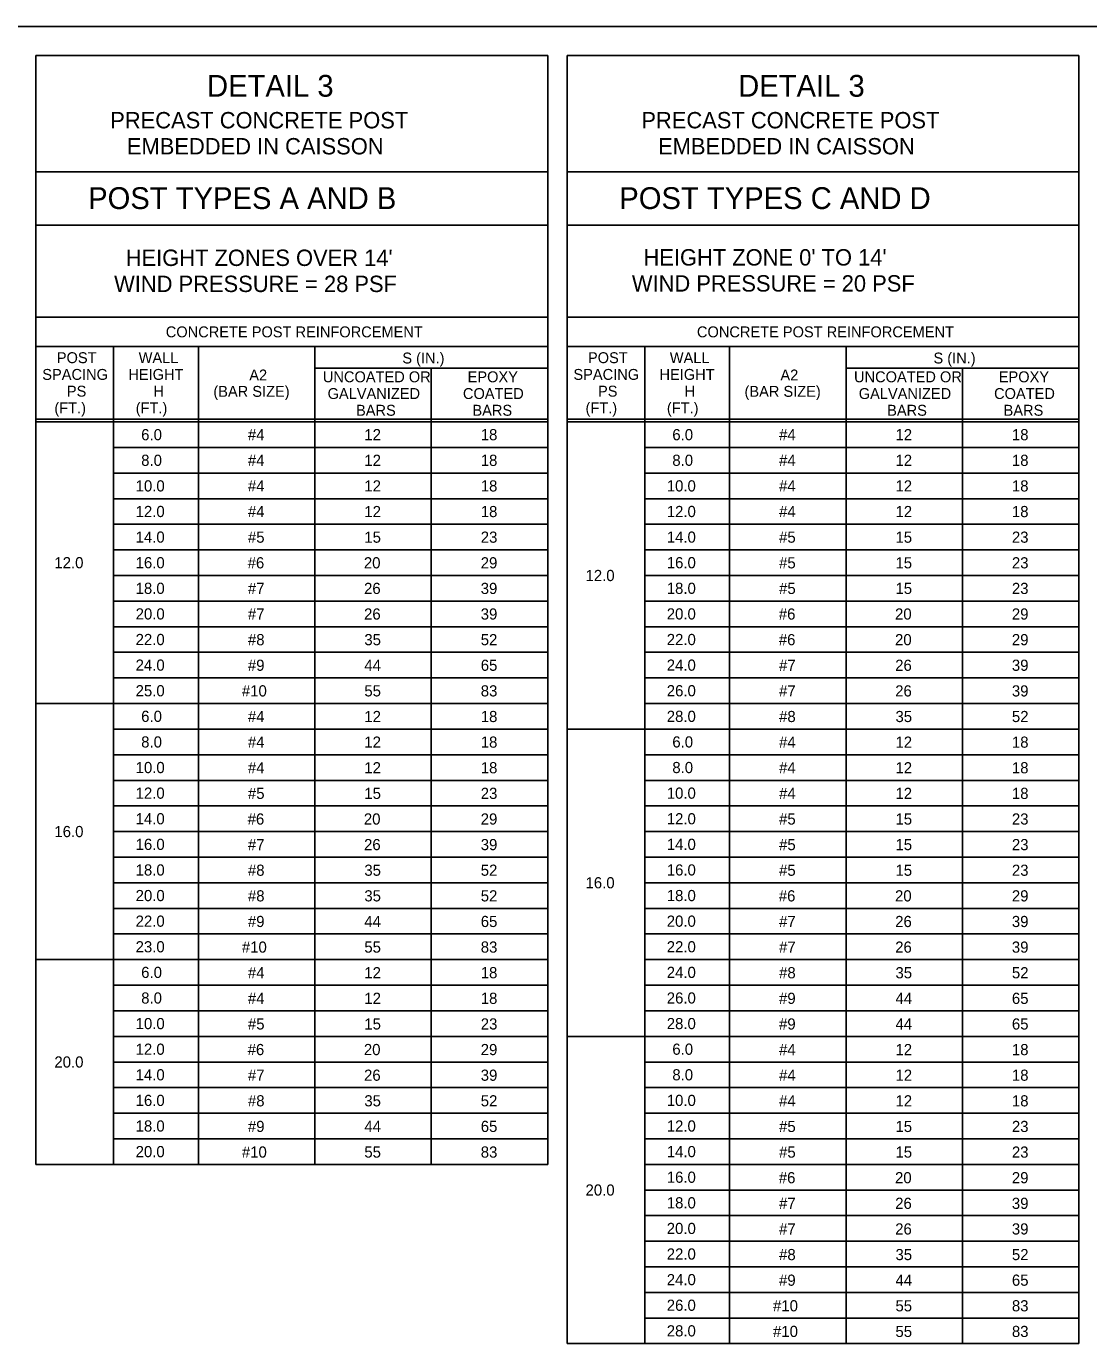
# Model space of a CAD drawing. Extents: x 3351 to 8430, y -3586 to 1457.
# Drawn here: x 4793.7 to 5085.7, y -1587.5 to -1225.3 of the extents above; entities that cross this region are included whole.
import ezdxf

# ---------------------------------------------------------------- set-up
doc = ezdxf.new("R2010")
doc.units = 0
doc.layers.add('1', color=7, linetype='Continuous')
doc.layers.add('2', color=7, linetype='Continuous')

msp = doc.modelspace()

# ---------------------------------------------------------------- linework, layer by layer
at = {"layer": '1'}
for p, q in [((4796.34, -1233.31), (4796.34, -1538.22)), ((4937.01, -1233.31), (4796.34, -1233.31)), ((4937.01, -1233.31), (4937.01, -1538.22)), ((4942.34, -1233.31), (4942.34, -1587.5)), ((5083.01, -1233.31), (4942.34, -1233.31)), ((5083.01, -1233.31), (5083.01, -1587.5)), ((4937.01, -1265.31), (4796.34, -1265.31)), ((5083.01, -1265.31), (4942.34, -1265.31)), ((4796.34, -1280.01), (4937.01, -1280.01)), ((4942.34, -1280.01), (5083.01, -1280.01)), ((4796.34, -1305.31), (4937.01, -1305.31)), ((4796.34, -1305.31), (4869.68, -1305.31)), ((4942.34, -1305.31), (5083.01, -1305.31)), ((4942.34, -1305.31), (5015.68, -1305.31)), ((4796.34, -1313.31), (4937.01, -1313.31)), ((4817.68, -1538.22), (4817.68, -1313.31)), ((4841.01, -1313.31), (4841.01, -1538.22)), ((4873.01, -1313.31), (4873.01, -1538.22)), ((4942.34, -1313.31), (5083.01, -1313.31)), ((4963.68, -1587.5), (4963.68, -1313.31)), ((4987.01, -1313.31), (4987.01, -1587.5)), ((5019.01, -1313.31), (5019.01, -1587.5)), ((4937.05, -1319.31), (4873.05, -1319.31)), ((4905.01, -1319.31), (4905.01, -1538.22)), ((5083.05, -1319.31), (5019.05, -1319.31)), ((5051.01, -1319.31), (5051.01, -1587.5)), ((4796.34, -1333.31), (4937.01, -1333.31)), ((4796.34, -1334.06), (4937.01, -1334.06)), ((4942.34, -1333.31), (5083.01, -1333.31)), ((4942.34, -1334.06), (5083.01, -1334.06)), ((4857.01, -1337.58), (4857.01, -1337.58)), ((4889.01, -1337.58), (4889.01, -1337.58)), ((4921.01, -1337.58), (4921.01, -1337.58)), ((5003.01, -1337.58), (5003.01, -1337.58)), ((5035.01, -1337.58), (5035.01, -1337.58)), ((5067.01, -1337.58), (5067.01, -1337.58)), ((4817.68, -1341.1), (4937.01, -1341.1)), ((4963.68, -1341.1), (5083.01, -1341.1)), ((4817.68, -1348.14), (4937.01, -1348.14)), ((4963.68, -1348.14), (5083.01, -1348.14)), ((4817.68, -1355.18), (4937.01, -1355.18)), ((4963.68, -1355.18), (5083.01, -1355.18)), ((4817.68, -1362.22), (4937.01, -1362.22)), ((4963.68, -1362.22), (5083.01, -1362.22)), ((4817.68, -1369.26), (4937.01, -1369.26)), ((4963.68, -1369.26), (5083.01, -1369.26)), ((4817.68, -1376.3), (4937.01, -1376.3)), ((4963.68, -1376.3), (5083.01, -1376.3)), ((4817.68, -1383.34), (4937.01, -1383.34)), ((4963.68, -1383.34), (5083.01, -1383.34)), ((4817.68, -1390.38), (4937.01, -1390.38)), ((4963.68, -1390.38), (5083.01, -1390.38)), ((4817.68, -1397.42), (4937.01, -1397.42)), ((4963.68, -1397.42), (5083.01, -1397.42)), ((4817.68, -1404.46), (4937.01, -1404.46)), ((4963.68, -1404.46), (5083.01, -1404.46)), ((4796.34, -1411.5), (4937.01, -1411.5)), ((4796.34, -1411.5), (4937.01, -1411.5)), ((4963.68, -1411.5), (5083.01, -1411.5)), ((4857.01, -1415.02), (4857.01, -1415.02)), ((4889.01, -1415.02), (4889.01, -1415.02)), ((4921.01, -1415.02), (4921.01, -1415.02)), ((4817.68, -1418.54), (4937.01, -1418.54)), ((4942.34, -1418.54), (5083.01, -1418.54)), ((5003.01, -1422.06), (5003.01, -1422.06)), ((5035.01, -1422.06), (5035.01, -1422.06)), ((5067.01, -1422.06), (5067.01, -1422.06)), ((4817.68, -1425.58), (4937.01, -1425.58)), ((4963.68, -1425.58), (5083.01, -1425.58)), ((4817.68, -1432.62), (4937.01, -1432.62)), ((4963.68, -1432.62), (5083.01, -1432.62)), ((4817.68, -1439.66), (4937.01, -1439.66)), ((4963.68, -1439.66), (5083.01, -1439.66)), ((4817.68, -1446.7), (4937.01, -1446.7)), ((4963.68, -1446.7), (5083.01, -1446.7)), ((4817.68, -1453.74), (4937.01, -1453.74)), ((4963.68, -1453.74), (5083.01, -1453.74)), ((4817.68, -1460.78), (4937.01, -1460.78)), ((4963.68, -1460.78), (5083.01, -1460.78)), ((4817.68, -1467.82), (4937.01, -1467.82)), ((4963.68, -1467.82), (5083.01, -1467.82)), ((4817.68, -1474.86), (4937.01, -1474.86)), ((4963.68, -1474.86), (5083.01, -1474.86)), ((4796.34, -1481.9), (4937.01, -1481.9)), ((4963.68, -1481.9), (5083.01, -1481.9)), ((4857.01, -1485.42), (4857.01, -1485.42)), ((4889.01, -1485.42), (4889.01, -1485.42)), ((4921.01, -1485.42), (4921.01, -1485.42)), ((4817.68, -1488.94), (4937.01, -1488.94)), ((4817.68, -1488.94), (4937.01, -1488.94)), ((4963.68, -1488.94), (5083.01, -1488.94)), ((4817.68, -1495.98), (4937.01, -1495.98)), ((4963.68, -1495.98), (5083.01, -1495.98)), ((4817.68, -1503.02), (4937.01, -1503.02)), ((4942.34, -1503.02), (5083.01, -1503.02)), ((4942.34, -1503.02), (5083.01, -1503.02)), ((5003.01, -1506.54), (5003.01, -1506.54)), ((5035.01, -1506.54), (5035.01, -1506.54)), ((5067.01, -1506.54), (5067.01, -1506.54)), ((4817.68, -1510.06), (4937.01, -1510.06)), ((4963.68, -1510.06), (5083.01, -1510.06)), ((4963.68, -1510.06), (5083.01, -1510.06)), ((4817.68, -1517.1), (4937.01, -1517.1)), ((4963.68, -1517.1), (5083.01, -1517.1)), ((4817.68, -1524.14), (4937.01, -1524.14)), ((4963.68, -1524.14), (5083.01, -1524.14)), ((4817.68, -1531.18), (4937.01, -1531.18)), ((4963.68, -1531.18), (5083.01, -1531.18)), ((4796.34, -1538.22), (4937.01, -1538.22)), ((4963.68, -1538.22), (5083.01, -1538.22)), ((4963.68, -1545.26), (5083.01, -1545.26)), ((4963.68, -1552.3), (5083.01, -1552.3)), ((4963.68, -1559.34), (5083.01, -1559.34)), ((4963.68, -1566.38), (5083.01, -1566.38)), ((4963.68, -1573.42), (5083.01, -1573.42)), ((4963.68, -1580.46), (5083.01, -1580.46)), ((4942.34, -1587.5), (5083.01, -1587.5))]:
    msp.add_line(p, q, dxfattribs=at)
at = {"layer": '2'}
msp.add_line((4642.34, -1225.31), (5428.34, -1225.31), dxfattribs=at)

# ---------------------------------------------------------------- texts
at = {"layer": '1'}
for s, height, p in [('DETAIL 3', 6, (4843.36, -1244.66)), ('DETAIL 3', 6, (4989.36, -1244.66)), ('PRECAST CONCRETE POST', 4.5, (4816.75, -1253.36)), ('PRECAST CONCRETE POST', 4.5, (4962.75, -1253.36)), ('EMBEDDED IN CAISSON', 4.5, (4821.34, -1260.52)), ('EMBEDDED IN CAISSON', 4.5, (4967.34, -1260.52)), ('POST TYPES A AND B', 6, (4810.68, -1275.54)), ('POST TYPES C AND D', 6, (4956.68, -1275.54)), ("HEIGHT ZONES OVER 14'", 4.5, (4821.01, -1291.19)), ("HEIGHT ZONE 0' TO 14'", 4.5, (4963.33, -1291.07)), ('WIND PRESSURE = 28 PSF', 4.5, (4817.82, -1298.36)), ('WIND PRESSURE = 20 PSF', 4.5, (4960.14, -1298.23)), ('CONCRETE POST REINFORCEMENT', 3, (4832.02, -1310.81)), ('CONCRETE POST REINFORCEMENT', 3, (4978.02, -1310.81)), ('POST', 3, (4802.07, -1317.91)), ('WALL', 3, (4824.56, -1317.91)), ('S (IN.)', 3, (4897.04, -1318)), ('POST', 3, (4948.07, -1317.91)), ('WALL', 3, (4970.56, -1317.91)), ('S (IN.)', 3, (5043.04, -1318)), ('SPACING', 3, (4798.07, -1322.51)), ('HEIGHT', 3, (4821.73, -1322.51)), ('A2', 3, (4854.97, -1322.67)), ('UNCOATED OR', 3, (4875.2, -1323.17)), ('EPOXY', 3, (4914.99, -1323.17)), ('SPACING', 3, (4944.07, -1322.51)), ('HEIGHT', 3, (4967.73, -1322.51)), ('A2', 3, (5000.97, -1322.67)), ('UNCOATED OR', 3, (5021.2, -1323.17)), ('EPOXY', 3, (5060.99, -1323.17)), ('PS', 3, (4804.83, -1327.11)), ('H', 3, (4828.61, -1327.11)), ('(BAR SIZE)', 3, (4845.1, -1327.17)), ('GALVANIZED', 3, (4876.5, -1327.77)), ('COATED', 3, (4913.7, -1327.77)), ('PS', 3, (4950.83, -1327.11)), ('H', 3, (4974.61, -1327.11)), ('(BAR SIZE)', 3, (4991.1, -1327.17)), ('GALVANIZED', 3, (5022.5, -1327.77)), ('COATED', 3, (5059.7, -1327.77)), ('(FT.)', 3, (4801.4, -1331.71)), ('(FT.)', 3, (4823.76, -1331.71)), ('(FT.)', 3, (4947.4, -1331.71)), ('(FT.)', 3, (4969.76, -1331.71)), ('BARS', 3, (4884.31, -1332.37)), ('BARS', 3, (4916.31, -1332.37)), ('BARS', 3, (5030.31, -1332.37)), ('BARS', 3, (5062.31, -1332.37)), ('6.0', 3.07, (4825.26, -1339.11)), ('#4', 3.07, (4854.6, -1339.11)), ('12', 3.07, (4886.6, -1339.11)), ('18', 3.07, (4918.6, -1339.11)), ('6.0', 3.07, (4971.26, -1339.11)), ('#4', 3.07, (5000.6, -1339.11)), ('12', 3.07, (5032.6, -1339.11)), ('18', 3.07, (5064.6, -1339.11)), ('8.0', 3.07, (4825.26, -1346.15)), ('#4', 3.07, (4854.6, -1346.16)), ('12', 3.07, (4886.6, -1346.16)), ('18', 3.07, (4918.6, -1346.16)), ('8.0', 3.07, (4971.26, -1346.15)), ('#4', 3.07, (5000.6, -1346.16)), ('12', 3.07, (5032.6, -1346.16)), ('18', 3.07, (5064.6, -1346.16)), ('10.0', 3.07, (4823.73, -1353.19)), ('#4', 3.07, (4854.6, -1353.2)), ('12', 3.07, (4886.6, -1353.2)), ('18', 3.07, (4918.6, -1353.2)), ('10.0', 3.07, (4969.73, -1353.19)), ('#4', 3.07, (5000.6, -1353.2)), ('12', 3.07, (5032.6, -1353.2)), ('18', 3.07, (5064.6, -1353.2)), ('12.0', 3.07, (4823.73, -1360.23)), ('#4', 3.07, (4854.6, -1360.25)), ('12', 3.07, (4886.6, -1360.25)), ('18', 3.07, (4918.6, -1360.25)), ('12.0', 3.07, (4969.73, -1360.23)), ('#4', 3.07, (5000.6, -1360.25)), ('12', 3.07, (5032.6, -1360.25)), ('18', 3.07, (5064.6, -1360.25)), ('14.0', 3.07, (4823.73, -1367.27)), ('#5', 3.07, (4854.6, -1367.29)), ('15', 3.07, (4886.6, -1367.29)), ('23', 3.07, (4918.6, -1367.29)), ('14.0', 3.07, (4969.73, -1367.27)), ('#5', 3.07, (5000.6, -1367.29)), ('15', 3.07, (5032.6, -1367.29)), ('23', 3.07, (5064.6, -1367.29)), ('12.0', 3.07, (4801.4, -1374.31)), ('16.0', 3.07, (4823.73, -1374.31)), ('#6', 3.07, (4854.52, -1374.34)), ('20', 3.07, (4886.47, -1374.34)), ('29', 3.07, (4918.59, -1374.34)), ('16.0', 3.07, (4969.73, -1374.31)), ('#5', 3.07, (5000.6, -1374.34)), ('15', 3.07, (5032.6, -1374.34)), ('23', 3.07, (5064.6, -1374.34)), ('12.0', 3.07, (4947.4, -1377.83)), ('18.0', 3.07, (4823.73, -1381.35)), ('#7', 3.07, (4854.6, -1381.38)), ('26', 3.07, (4886.52, -1381.38)), ('39', 3.07, (4918.59, -1381.38)), ('18.0', 3.07, (4969.73, -1381.35)), ('#5', 3.07, (5000.6, -1381.38)), ('15', 3.07, (5032.6, -1381.38)), ('23', 3.07, (5064.6, -1381.38)), ('20.0', 3.07, (4823.73, -1388.39)), ('#7', 3.07, (4854.6, -1388.42)), ('26', 3.07, (4886.52, -1388.42)), ('39', 3.07, (4918.59, -1388.42)), ('20.0', 3.07, (4969.73, -1388.39)), ('#6', 3.07, (5000.52, -1388.42)), ('20', 3.07, (5032.47, -1388.42)), ('29', 3.07, (5064.59, -1388.42)), ('22.0', 3.07, (4823.73, -1395.43)), ('#8', 3.07, (4854.6, -1395.47)), ('35', 3.07, (4886.6, -1395.47)), ('52', 3.07, (4918.6, -1395.47)), ('22.0', 3.07, (4969.73, -1395.43)), ('#6', 3.07, (5000.52, -1395.47)), ('20', 3.07, (5032.47, -1395.47)), ('29', 3.07, (5064.59, -1395.47)), ('24.0', 3.07, (4823.73, -1402.47)), ('#9', 3.07, (4854.59, -1402.51)), ('44', 3.07, (4886.6, -1402.51)), ('65', 3.07, (4918.6, -1402.51)), ('24.0', 3.07, (4969.73, -1402.47)), ('#7', 3.07, (5000.6, -1402.51)), ('26', 3.07, (5032.52, -1402.51)), ('39', 3.07, (5064.59, -1402.51)), ('25.0', 3.07, (4823.73, -1409.51)), ('#10', 3.07, (4852.94, -1409.55)), ('55', 3.07, (4886.6, -1409.55)), ('83', 3.07, (4918.6, -1409.55)), ('26.0', 3.07, (4969.73, -1409.51)), ('#7', 3.07, (5000.6, -1409.56)), ('26', 3.07, (5032.52, -1409.56)), ('39', 3.07, (5064.59, -1409.56)), ('6.0', 3.07, (4825.26, -1416.55)), ('#4', 3.07, (4854.6, -1416.6)), ('12', 3.07, (4886.6, -1416.6)), ('18', 3.07, (4918.6, -1416.6)), ('28.0', 3.07, (4969.73, -1416.55)), ('#8', 3.07, (5000.6, -1416.6)), ('35', 3.07, (5032.6, -1416.6)), ('52', 3.07, (5064.6, -1416.6)), ('8.0', 3.07, (4825.26, -1423.59)), ('#4', 3.07, (4854.6, -1423.64)), ('12', 3.07, (4886.6, -1423.64)), ('18', 3.07, (4918.6, -1423.64)), ('6.0', 3.07, (4971.26, -1423.59)), ('#4', 3.07, (5000.6, -1423.65)), ('12', 3.07, (5032.6, -1423.65)), ('18', 3.07, (5064.6, -1423.65)), ('10.0', 3.07, (4823.73, -1430.63)), ('#4', 3.07, (4854.6, -1430.69)), ('12', 3.07, (4886.6, -1430.69)), ('18', 3.07, (4918.6, -1430.69)), ('8.0', 3.07, (4971.26, -1430.63)), ('#4', 3.07, (5000.6, -1430.69)), ('12', 3.07, (5032.6, -1430.69)), ('18', 3.07, (5064.6, -1430.69)), ('12.0', 3.07, (4823.73, -1437.67)), ('#5', 3.07, (4854.6, -1437.73)), ('15', 3.07, (4886.6, -1437.73)), ('23', 3.07, (4918.6, -1437.73)), ('10.0', 3.07, (4969.73, -1437.67)), ('#4', 3.07, (5000.6, -1437.74)), ('12', 3.07, (5032.6, -1437.74)), ('18', 3.07, (5064.6, -1437.74)), ('16.0', 3.07, (4801.4, -1448.23)), ('14.0', 3.07, (4823.73, -1444.71)), ('#6', 3.07, (4854.52, -1444.78)), ('20', 3.07, (4886.47, -1444.78)), ('29', 3.07, (4918.59, -1444.78)), ('12.0', 3.07, (4969.73, -1444.71)), ('#5', 3.07, (5000.6, -1444.78)), ('15', 3.07, (5032.6, -1444.78)), ('23', 3.07, (5064.6, -1444.78)), ('16.0', 3.07, (4823.73, -1451.75)), ('#7', 3.07, (4854.6, -1451.82)), ('26', 3.07, (4886.52, -1451.82)), ('39', 3.07, (4918.59, -1451.82)), ('14.0', 3.07, (4969.73, -1451.75)), ('#5', 3.07, (5000.6, -1451.82)), ('15', 3.07, (5032.6, -1451.82)), ('23', 3.07, (5064.6, -1451.82)), ('18.0', 3.07, (4823.73, -1458.79)), ('#8', 3.07, (4854.6, -1458.86)), ('35', 3.07, (4886.6, -1458.86)), ('52', 3.07, (4918.6, -1458.86)), ('16.0', 3.07, (4969.73, -1458.79)), ('#5', 3.07, (5000.6, -1458.87)), ('15', 3.07, (5032.6, -1458.87)), ('23', 3.07, (5064.6, -1458.87)), ('16.0', 3.07, (4947.4, -1462.31)), ('20.0', 3.07, (4823.73, -1465.83)), ('#8', 3.07, (4854.6, -1465.91)), ('35', 3.07, (4886.6, -1465.91)), ('52', 3.07, (4918.6, -1465.91)), ('18.0', 3.07, (4969.73, -1465.83)), ('#6', 3.07, (5000.52, -1465.91)), ('20', 3.07, (5032.47, -1465.91)), ('29', 3.07, (5064.59, -1465.91)), ('22.0', 3.07, (4823.73, -1472.87)), ('#9', 3.07, (4854.59, -1472.95)), ('44', 3.07, (4886.6, -1472.95)), ('65', 3.07, (4918.6, -1472.95)), ('20.0', 3.07, (4969.73, -1472.87)), ('#7', 3.07, (5000.6, -1472.96)), ('26', 3.07, (5032.52, -1472.96)), ('39', 3.07, (5064.59, -1472.96)), ('23.0', 3.07, (4823.73, -1479.91)), ('#10', 3.07, (4852.94, -1479.99)), ('55', 3.07, (4886.6, -1479.99)), ('83', 3.07, (4918.6, -1479.99)), ('22.0', 3.07, (4969.73, -1479.91)), ('#7', 3.07, (5000.6, -1480)), ('26', 3.07, (5032.52, -1480)), ('39', 3.07, (5064.59, -1480)), ('6.0', 3.07, (4825.26, -1486.95)), ('#4', 3.07, (4854.6, -1487.04)), ('12', 3.07, (4886.6, -1487.04)), ('18', 3.07, (4918.6, -1487.04)), ('24.0', 3.07, (4969.73, -1486.95)), ('#8', 3.07, (5000.6, -1487.05)), ('35', 3.07, (5032.6, -1487.05)), ('52', 3.07, (5064.6, -1487.05)), ('8.0', 3.07, (4825.26, -1493.99)), ('#4', 3.07, (4854.6, -1494.08)), ('12', 3.07, (4886.6, -1494.08)), ('18', 3.07, (4918.6, -1494.08)), ('26.0', 3.07, (4969.73, -1493.99)), ('#9', 3.07, (5000.59, -1494.09)), ('44', 3.07, (5032.6, -1494.09)), ('65', 3.07, (5064.6, -1494.09)), ('10.0', 3.07, (4823.73, -1501.03)), ('#5', 3.07, (4854.6, -1501.13)), ('15', 3.07, (4886.6, -1501.13)), ('23', 3.07, (4918.6, -1501.13)), ('28.0', 3.07, (4969.73, -1501.03)), ('#9', 3.07, (5000.59, -1501.14)), ('44', 3.07, (5032.6, -1501.14)), ('65', 3.07, (5064.6, -1501.14)), ('12.0', 3.07, (4823.73, -1508.07)), ('#6', 3.07, (4854.52, -1508.17)), ('20', 3.07, (4886.47, -1508.17)), ('29', 3.07, (4918.59, -1508.17)), ('6.0', 3.07, (4971.26, -1508.07)), ('#4', 3.07, (5000.6, -1508.18)), ('12', 3.07, (5032.6, -1508.18)), ('18', 3.07, (5064.6, -1508.18)), ('20.0', 3.07, (4801.4, -1511.59)), ('14.0', 3.07, (4823.73, -1515.11)), ('#7', 3.07, (4854.6, -1515.22)), ('26', 3.07, (4886.52, -1515.22)), ('39', 3.07, (4918.59, -1515.22)), ('8.0', 3.07, (4971.26, -1515.11)), ('#4', 3.07, (5000.6, -1515.22)), ('12', 3.07, (5032.6, -1515.22)), ('18', 3.07, (5064.6, -1515.22)), ('16.0', 3.07, (4823.73, -1522.15)), ('#8', 3.07, (4854.6, -1522.26)), ('35', 3.07, (4886.6, -1522.26)), ('52', 3.07, (4918.6, -1522.26)), ('10.0', 3.07, (4969.73, -1522.15)), ('#4', 3.07, (5000.6, -1522.27)), ('12', 3.07, (5032.6, -1522.27)), ('18', 3.07, (5064.6, -1522.27)), ('18.0', 3.07, (4823.73, -1529.19)), ('#9', 3.07, (4854.59, -1529.3)), ('44', 3.07, (4886.6, -1529.3)), ('65', 3.07, (4918.6, -1529.3)), ('12.0', 3.07, (4969.73, -1529.19)), ('#5', 3.07, (5000.6, -1529.31)), ('15', 3.07, (5032.6, -1529.31)), ('23', 3.07, (5064.6, -1529.31)), ('20.0', 3.07, (4823.73, -1536.23)), ('#10', 3.07, (4852.94, -1536.35)), ('55', 3.07, (4886.6, -1536.35)), ('83', 3.07, (4918.6, -1536.35)), ('14.0', 3.07, (4969.73, -1536.23)), ('#5', 3.07, (5000.6, -1536.36)), ('15', 3.07, (5032.6, -1536.36)), ('23', 3.07, (5064.6, -1536.36)), ('16.0', 3.07, (4969.73, -1543.27)), ('#6', 3.07, (5000.52, -1543.4)), ('20', 3.07, (5032.47, -1543.4)), ('29', 3.07, (5064.59, -1543.4)), ('20.0', 3.07, (4947.4, -1546.79)), ('18.0', 3.07, (4969.73, -1550.31)), ('#7', 3.07, (5000.6, -1550.45)), ('26', 3.07, (5032.52, -1550.45)), ('39', 3.07, (5064.59, -1550.45)), ('20.0', 3.07, (4969.73, -1557.35)), ('#7', 3.07, (5000.6, -1557.49)), ('26', 3.07, (5032.52, -1557.49)), ('39', 3.07, (5064.59, -1557.49)), ('22.0', 3.07, (4969.73, -1564.39)), ('#8', 3.07, (5000.6, -1564.54)), ('35', 3.07, (5032.6, -1564.54)), ('52', 3.07, (5064.6, -1564.54)), ('24.0', 3.07, (4969.73, -1571.43)), ('#9', 3.07, (5000.59, -1571.58)), ('44', 3.07, (5032.6, -1571.58)), ('65', 3.07, (5064.6, -1571.58)), ('26.0', 3.07, (4969.73, -1578.47)), ('#10', 3.07, (4998.94, -1578.62)), ('83', 3.07, (5064.6, -1578.62)), ('55', 3.07, (5032.6, -1578.62)), ('28.0', 3.07, (4969.73, -1585.51)), ('#10', 3.07, (4998.94, -1585.67)), ('55', 3.07, (5032.6, -1585.67)), ('83', 3.07, (5064.6, -1585.67))]:
    msp.add_text(s, height=height, dxfattribs=at).set_placement(p)

doc.saveas('drawing.dxf')
